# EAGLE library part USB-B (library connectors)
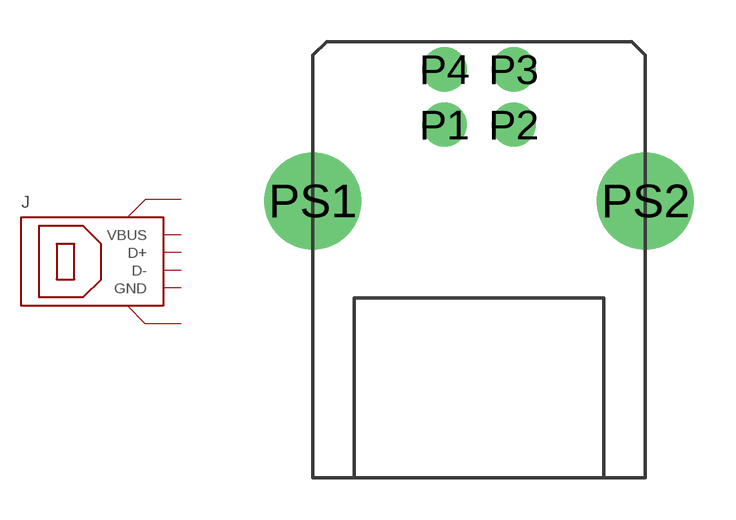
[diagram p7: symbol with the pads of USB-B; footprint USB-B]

Designator prefix J

## USB-B  [USB-B]
P1  D+
P2  GND  pwr
P3  VBUS  pwr
P4  D-
PS1  SCREEN  pas
PS2  SCREEN  pas

## Footprint USB-B (pad centres in mm)
drill 1.05 pad 1.6 round: P1 -1.25,0; P2 1.25,0; P3 1.25,2; P4 -1.25,2
drill 2 pad 3.5 round: PS1 -6,-2.75; PS2 6,-2.75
